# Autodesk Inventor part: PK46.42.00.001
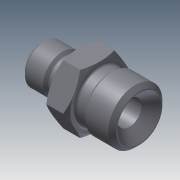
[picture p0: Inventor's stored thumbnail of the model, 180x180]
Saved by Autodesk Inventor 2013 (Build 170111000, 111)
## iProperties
Created: 2005-06
Part Number: PK46.42.00.001
Material: Steel, Mild
Document SubType Name: Modeling
Designer: salex
Manufacturer: Standard
Standards Organization: Custom
Density: 7.86 g/cm^3
Mass: 73.9851 g
Surface Area: 45.5262 cm^2
Volume: 9.41287 cm^3
Author: salex
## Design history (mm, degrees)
sketch "Эскиз1"
  geometry: L1 (0, 0)-(44.165, 0); L2 (0, 5)-(0, 8); L3 (0, 8)-(8.9, 8); L4 (8.9, 8)-(10, 6.9); L5 (10, 6.9)-(14, 6.9); L6 (14, 6.9)-(14, 8); L7 (14, 8)-(15, 8); L8 (15, 8)-(15, 12); L9 (15, 12)-(16.732, 15); L10 (16.732, 15)-(22.268, 15); L11 (22.268, 15)-(24, 12); L12 (24, 12)-(24, 9.9); L13 (24, 9.9)-(28, 9.9); L14 (28, 9.9)-(29.1, 11); L15 (29.1, 11)-(40, 11); L16 (40, 11)-(40, 9); L17 (40, 9)-(36, 5); L18 (36, 5)-(0, 5)
  constraints: 36 end point, 9 parallel, 2 perpendicular, 1 collinear, 1 equal length, 1 horizontal, 1 other
  dimensions: "d0" = 0 distance from line of L1.start L2; "d1" = 15 distance between parallel lines of L8 L2; "d2" = 40 distance between parallel lines of L16 L2; "d3" = 16 distance between parallel lines of L16 L12; "d4" = 30 diameter of L10 L1; "d5" = 10 diameter of L18 L1; "d6" = 45 deg angle of L18 L17; "d7" = 18 diameter of L16.end L1; "d8" = 22 diameter of L15 L1; "d9" = 19.8 diameter of L13 L1; "d10" = 45 deg angle of L14 L13; "d11" = 4 distance of L12.end L13.end; "d12" = 16 diameter of L3 L1; "d13" = 13.8 diameter of L5 L1; "d14" = 4 distance of L4.end L5.end; "d15" = 1 distance of L6.end L7.end; "d16" = 16 diameter of L7 L1; "d17" = 45 deg angle of L5 L4; "d18" = 24 diameter of L8.end L1; "d19" = 0 vertical distance of L8.end L11.end; "d20" = 30 deg angle of L8 L9
revolve "Вращение1" sketch "Эскиз1" stored, may be unused: angle "d21" = 90 deg
chamfer "Фаска1" distance "d22" = 1.6; stored, may be unused: second distance "d23" = 2, angle "d24" = 45 deg
fillet "Сопряжение1" dims "d25" = 1
fillet "Сопряжение2" dims "d26" = 0.5
sketch "Эскиз2"
  geometry: L1 (0, 13.856)-(12, 6.928); L2 (12, 6.928)-(12, -6.928); L3 (12, -6.928)-(0, -13.856); L4 (0, -13.856)-(-12, -6.928); L5 (-12, -6.928)-(-12, 6.928); L6 (-12, 6.928)-(0, 13.856); C1 r 6.4 at (0, 0) reference; 1 further point
  constraints: 12 end point, 1 coincident, 11 other
  dimensions: "d27" = 24 distance between parallel lines of L2 L5
extrude "Выдавливание1" sketch "Эскиз2" stored distance "d28" = 10; taper "d29" = 0 deg
body "Solid1"
